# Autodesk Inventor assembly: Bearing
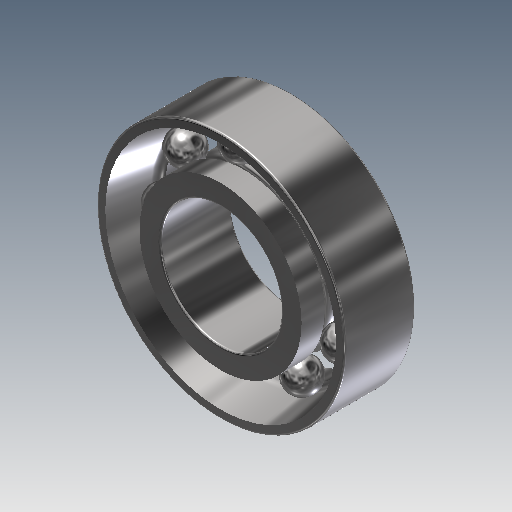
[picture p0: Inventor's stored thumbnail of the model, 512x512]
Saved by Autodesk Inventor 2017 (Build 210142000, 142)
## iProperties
ClientObjectVersion: 1
Created: 2019-02
Part Number: Bearing
Document SubType Name: Assembly
Designer: user
Author: user
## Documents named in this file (2)
- C:\Users\user\Desktop\Ensamble reductor de velocidad\Ensamble\Design Accelerator\Bearing2.iam
- C:\Users\user\Documents\Inventor\Content Center Files\R2017\en-US\BS 292 (II)\BS 292_ Part 1 - 7003 - 17 x 35 x 10.ipt
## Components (1 placed, 1 different names)
1. BS 292: Part 1 (II) - Metric 7003 - 17 x 35 x 10:1
